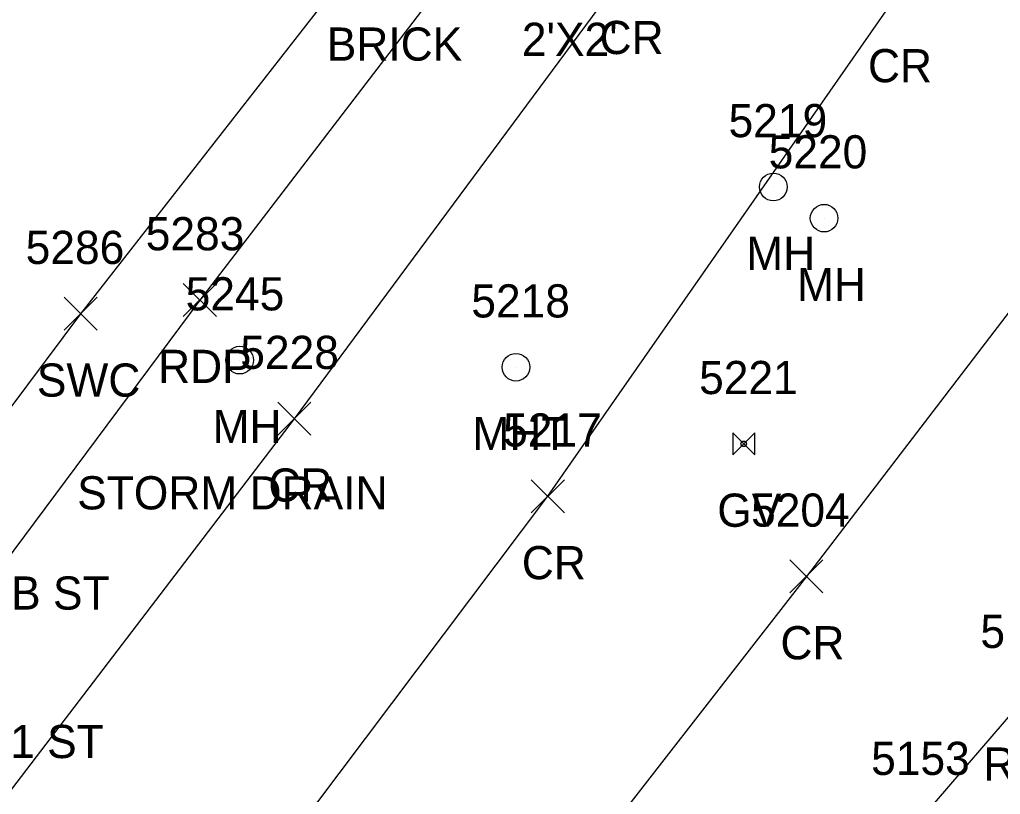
# Model space of a CAD drawing. Extents: x 1618146 to 1620418, y 640749 to 641927.
# Drawn here: x 1620288.8 to 1620347.9, y 640989.8 to 641036.5 of the extents above; entities that cross this region are included whole.
import ezdxf

# ---------------------------------------------------------------- set-up
doc = ezdxf.new("R2010")
doc.units = 0
for name, color, linetype in [('D_C', 7, 'Continuous'), ('L_C', 7, 'Continuous'), ('P_A', 7, 'Continuous'), ('P_I', 7, 'Continuous'), ('P_TIC', 7, 'Continuous'), ('PET', 7, 'Continuous'), ('PRC', 7, 'Continuous'), ('R_A', 7, 'Continuous'), ('R_I', 7, 'Continuous'), ('R_TIC', 7, 'Continuous'), ('RSW', 7, 'Continuous'), ('U_A', 7, 'Continuous'), ('U_C', 7, 'Continuous'), ('U_I', 7, 'Continuous'), ('UTMH', 7, 'Continuous'), ('UUMH', 7, 'Continuous'), ('UWV', 7, 'Continuous')]:
    doc.layers.add(name, color=color, linetype=linetype)

msp = doc.modelspace()

# ---------------------------------------------------------------- linework, layer by layer
at = {"layer": 'P_TIC'}
for points in [[(1620298.64, 641018.571), (1620300.64, 641020.571)], [(1620300.64, 641018.571), (1620298.64, 641020.571)], [(1620304.343, 641011.417), (1620306.343, 641013.417)], [(1620306.343, 641011.417), (1620304.343, 641013.417)], [(1620319.636, 641006.736), (1620321.636, 641008.736)], [(1620321.636, 641006.736), (1620319.636, 641008.736)], [(1620335.241, 641001.906), (1620337.241, 641003.906)], [(1620337.241, 641001.906), (1620335.241, 641003.906)]]:
    msp.add_lwpolyline(points, dxfattribs=at)
at = {"layer": 'PET'}
for points in [[(1620359.618, 641102.741), (1620357.552, 641099.276), (1620341.731, 641075.022), (1620339.541, 641071.666), (1620329.909, 641058.991), (1620323.975, 641051.239), (1620317.974, 641043.478), (1620299.64, 641019.571), (1620282.799, 640996.951), (1620281.456, 640995.25), (1620278.195, 640990.782), (1620276.89, 640989.311), (1620275.826, 640987.688), (1620269.888, 640979.335), (1620267.257, 640975.908), (1620246.8, 640948.475), (1620237.104, 640935.681), (1620207.924, 640898.413)], [(1620301.599, 640941.889), (1620306.673, 640947.652), (1620308.049, 640949.035), (1620313.723, 640955.551), (1620317.973, 640960.228), (1620327.197, 640970.287), (1620342.84, 640987.934), (1620349.43, 640995.592), (1620362.743, 641013.622), (1620363.905, 641016.91), (1620366.737, 641021.043), (1620371.936, 641023.376), (1620397.595, 641061.893), (1620399.294, 641063.904)]]:
    msp.add_lwpolyline(points, dxfattribs=at)
at = {"layer": 'PRC'}
for points in [[(1620362.761, 641090.181), (1620340.683, 641059.759), (1620325.328, 641039.403), (1620305.343, 641012.417), (1620285.981, 640987.098), (1620282.921, 640982.142), (1620262.646, 640955.357), (1620239.617, 640925.265), (1620211.715, 640891.88)], [(1620224.798, 640884.187), (1620252.423, 640919.672), (1620271.906, 640945.144), (1620290.437, 640967.965), (1620293.935, 640972.261), (1620320.636, 641007.736), (1620341.521, 641037.703), (1620358.234, 641062.028), (1620372.9, 641083.065)], [(1620386.404, 641071.706), (1620361.021, 641035.235), (1620336.241, 641002.906), (1620316.225, 640977.168), (1620300.323, 640960.311), (1620296.609, 640956.784), (1620272.862, 640927.85), (1620252.181, 640901.579), (1620233.904, 640877.595)]]:
    msp.add_lwpolyline(points, dxfattribs=at)
at = {"layer": 'R_TIC'}
for points in [[(1620291.451, 641017.745), (1620293.451, 641019.745)], [(1620293.451, 641017.745), (1620291.451, 641019.745)]]:
    msp.add_lwpolyline(points, dxfattribs=at)
at = {"layer": 'RSW'}
msp.add_lwpolyline([(1620349.334, 641111.084), (1620330.297, 641082.333), (1620335.893, 641078.821), (1620332.216, 641073.255), (1620323.175, 641059.004), (1620311.046, 641042.568), (1620292.451, 641018.745), (1620282.833, 641005.905)], dxfattribs=at)
at = {"layer": 'UTMH'}
for p, q in [((1620318.716, 641015.52), (1620318.716, 641015.52)), ((1620319.55, 641015.52), (1620319.55, 641015.52))]:
    msp.add_line(p, q, dxfattribs=at)
msp.add_circle((1620318.716, 641015.52), 0.833, dxfattribs=at)
at = {"layer": 'UUMH'}
for p, q in [((1620334.246, 641026.391), (1620334.246, 641026.391)), ((1620335.079, 641026.391), (1620335.079, 641026.391)), ((1620337.309, 641024.509), (1620337.309, 641024.509)), ((1620338.142, 641024.509), (1620338.142, 641024.509)), ((1620302.049, 641015.947), (1620302.049, 641015.947)), ((1620302.882, 641015.947), (1620302.882, 641015.947))]:
    msp.add_line(p, q, dxfattribs=at)
for centre in [(1620334.246, 641026.391), (1620337.309, 641024.509), (1620302.049, 641015.947)]:
    msp.add_circle(centre, 0.833, dxfattribs=at)
at = {"layer": 'UWV'}
for p, q in [((1620331.794, 641011.566), (1620333.128, 641010.232)), ((1620333.128, 641011.566), (1620331.794, 641010.232))]:
    msp.add_line(p, q, dxfattribs=at)
for points in [[(1620331.794, 641011.566), (1620331.794, 641010.232)], [(1620333.128, 641010.232), (1620333.128, 641011.566)]]:
    msp.add_lwpolyline(points, dxfattribs=at)
msp.add_circle((1620332.461, 641010.899), 0.167, dxfattribs=at)

# ---------------------------------------------------------------- texts
at = {"layer": 'D_C'}
msp.add_text("2'X2'", height=2, dxfattribs=at).set_placement((1620319.074, 641034.292))
at = {"layer": 'L_C'}
msp.add_text('BRICK', height=2, dxfattribs=at).set_placement((1620307.305, 641034.006))
msp.add_text('BRICK', height=2, dxfattribs=at).set_placement((1620307.305, 641034.006))
at = {"layer": 'P_A'}
for s, p in [('CR', (1620323.761, 641034.403)), ('CR', (1620339.954, 641032.703)), ('RDP', (1620297.128, 641014.571)), ('CR', (1620303.777, 641007.417)), ('CR', (1620319.069, 641002.736)), ('CR', (1620334.674, 640997.906)), ('RDP', (1620346.918, 640990.592))]:
    msp.add_text(s, height=2, dxfattribs=at).set_placement(p)
at = {"layer": 'P_I'}
for s, p in [('5283', (1620296.38, 641022.571)), ('5228', (1620302.084, 641015.417)), ('5217', (1620317.943, 641010.736)), ('5204', (1620332.903, 641005.906)), ('5154', (1620346.737, 640998.592)), ('5154', (1620346.737, 640998.592)), ('5153', (1620340.147, 640990.934)), ('5153', (1620340.147, 640990.934))]:
    msp.add_text(s, height=2, dxfattribs=at).set_placement(p)
at = {"layer": 'R_A'}
for s, p in [('SWC', (1620289.813, 641013.745)), ('SWC SWC1 RB ST', (1620270.873, 641000.905)), ('SWC SWC1 RB ST', (1620270.873, 641000.905)), ('RDP1 SWC1 ST', (1620274.083, 640991.951))]:
    msp.add_text(s, height=2, dxfattribs=at).set_placement(p)
at = {"layer": 'R_I'}
msp.add_text('5286', height=2, dxfattribs=at).set_placement((1620289.136, 641021.745))
at = {"layer": 'U_A'}
for s, p in [('MH', (1620332.608, 641021.391)), ('MH', (1620335.671, 641019.509)), ('MH', (1620300.411, 641010.947)), ('MHT', (1620316.094, 641010.52)), ('GV', (1620330.863, 641005.899))]:
    msp.add_text(s, height=2, dxfattribs=at).set_placement(p)
at = {"layer": 'U_C'}
msp.add_text('STORM DRAIN', height=2, dxfattribs=at).set_placement((1620292.246, 641006.947))
at = {"layer": 'U_I'}
for s, p in [('5219', (1620331.545, 641029.391)), ('5220', (1620333.963, 641027.509)), ('5245', (1620298.789, 641018.947)), ('5218', (1620316.024, 641018.52)), ('5221', (1620329.768, 641013.899))]:
    msp.add_text(s, height=2, dxfattribs=at).set_placement(p)

doc.saveas('drawing.dxf')
